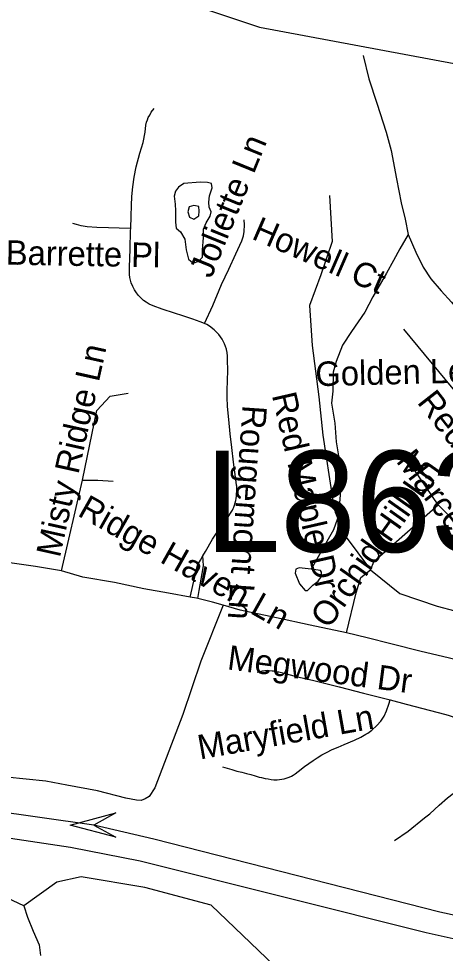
# Model space of a CAD drawing. Extents: x 1383679 to 1536984, y 460658 to 651027.
# Drawn here: x 1450610 to 1452269, y 483158 to 486789 of the extents above; entities that cross this region are included whole.
import ezdxf

# ---------------------------------------------------------------- set-up
doc = ezdxf.new("R2010")
doc.units = 0
for name, color, linetype in [('Exist Hydrographic Creek Single Shore', 7, 'Continuous'), ('Exist Hydrographic Misc Water Feature', 7, 'Continuous'), ('Exist Road Non-System Type 51', 7, 'Continuous'), ('Exist Road Non-System Type 51 Label', 7, 'Continuous'), ('Exist Road Primary Interstate Divided Center Attributed', 7, 'Continuous'), ('Exist Road Primary Interstate Structure Cantilever Sign Attributed CELL', 7, 'Continuous'), ('Exist Road Primary Interstate Structure Cantilever Sign Number Label', 7, 'Continuous')]:
    doc.layers.add(name, color=color, linetype=linetype)

msp = doc.modelspace()

# ---------------------------------------------------------------- linework, layer by layer
at = {"layer": 'Exist Hydrographic Creek Single Shore'}
for points in [[(1451305.3, 486835.8), (1451546.2, 486755.5), (1452401.3, 486597.1), (1452660.2, 486628), (1452879.2, 486715.5), (1453129.2, 486710.5), (1453286.3, 486658.1), (1453403.2, 486662.3), (1453504.2, 486735.7), (1454042.3, 487417.5)], [(1450631, 483341.9), (1450302.2, 483494.8), (1449922.4, 483518.4), (1449139, 483483.5), (1448970, 483355.2), (1448382.2, 482913), (1447997.1, 482655.5), (1447799, 482673.6), (1447552.4, 482785.6), (1447330.1, 482896.2), (1447225.8, 482956.7), (1446831, 483120.2), (1446515, 483238.6), (1446352.4, 483568.7), (1446248.7, 483809.2), (1446066, 484021), (1445953.2, 484107.5), (1445854.2, 484158.7)], [(1451604.2, 483110.8), (1451358.9, 483344.6), (1451101.1, 483413.1), (1450853.8, 483455.2), (1450759.1, 483434.2), (1450631, 483341.9)]]:
    msp.add_lwpolyline(points, dxfattribs=at)
at = {"layer": 'Exist Hydrographic Misc Water Feature'}
for points in [[(1451949.9, 486645.3), (1451972.3, 486555.4), (1452002.5, 486460.5), (1452038.5, 486348.1), (1452059.2, 486277.2), (1452079.2, 486166.8), (1452097.4, 486072.9), (1452112.4, 486010.2), (1452125.2, 485950.1)], [(1451316.6, 486153.4), (1451252.5, 486148.1), (1451232.2, 486134.6), (1451219.9, 486118.5), (1451215.5, 486098.8), (1451219, 486068.4), (1451220.5, 486043), (1451219.7, 485998.7), (1451223.3, 485974.8), (1451239.1, 485960.5), (1451256.5, 485932.2), (1451261.8, 485890.3), (1451271.1, 485854), (1451288.8, 485839.7), (1451311.1, 485846.6), (1451325.3, 485862.8), (1451325.7, 485889), (1451328.7, 485939), (1451329.2, 485971), (1451339.8, 485996.2), (1451354.3, 486022.2), (1451358.5, 486038.5), (1451350.9, 486056.7), (1451349.2, 486076.4), (1451351.7, 486100.2), (1451362.2, 486132), (1451360.5, 486148.4), (1451344.6, 486152.9), (1451316.6, 486153.4)], [(1451291, 486063.7), (1451272.8, 486057.5), (1451268.4, 486037.9), (1451274.1, 486018), (1451292, 486009.5), (1451310.3, 486023.1), (1451312.6, 486041.1), (1451311, 486059.1), (1451291, 486063.7)], [(1452125.2, 485950.1), (1452092.2, 485894.9), (1452067.4, 485849.4), (1452040.4, 485800), (1451986.8, 485708.3), (1451955.7, 485649), (1451904.3, 485573.7), (1451869.3, 485520.3), (1451844.2, 485456.8), (1451833.4, 485415.1), (1451832, 485341.3), (1451827.2, 485295.5), (1451839.8, 485217.3), (1451844.5, 485144.9), (1451853.4, 485090.6), (1451860, 485006.8), (1451860.7, 484938.6), (1451855.6, 484874.7), (1451848.9, 484842.9), (1451834.2, 484802.9), (1451803.2, 484749.4), (1451774.3, 484698.3), (1451747.4, 484650.4)], [(1452125.2, 485950.1), (1452154, 485881.4), (1452183, 485823.3), (1452212.2, 485778.4), (1452253.4, 485731.6), (1452292.6, 485687.4), (1452341.5, 485628.1), (1452392.1, 485550.8), (1452438.9, 485486.6), (1452476, 485433.4), (1452524.9, 485372.5), (1452571.8, 485314.1), (1452632.8, 485253), (1452672.1, 485213.6), (1452703.2, 485161.3), (1452720.3, 485115), (1452723.7, 485081.3), (1452713, 485043), (1452700.5, 485021), (1452661.8, 484974.2), (1452620.9, 484934.8), (1452590.3, 484899.3), (1452580, 484885.6)], [(1451747.4, 484650.4), (1451701.5, 484655.5), (1451687.3, 484650), (1451685.1, 484635.3), (1451702.3, 484593.1), (1451723.8, 484567.2), (1451733.9, 484567), (1451754.3, 484588.8), (1451774.6, 484603.9), (1451786.8, 484620.1), (1451787.2, 484638.1), (1451783.3, 484645.6), (1451747.4, 484650.4)], [(1450631, 483341.9), (1450644.1, 483298.1), (1450667.2, 483243.5), (1450690.3, 483191.3), (1450695.5, 483149.4)]]:
    msp.add_lwpolyline(points, dxfattribs=at)
at = {"layer": 'Exist Road Non-System Type 51'}
for points in [[(1451046, 485974), (1451047.5, 486021.8), (1451049.1, 486062.7), (1451050.9, 486098.6), (1451054.4, 486135.1), (1451059.9, 486173.8), (1451067.7, 486213.3), (1451081.4, 486266.7), (1451093.8, 486307.9), (1451102.2, 486348.3), (1451105.4, 486375.5), (1451108, 486386.5), (1451110.9, 486396.2), (1451114.1, 486404.4), (1451120.2, 486414.6), (1451125.8, 486425.2), (1451137.1, 486440.6)], [(1451818.5, 486101.7), (1451829.6, 485923.7), (1451785.1, 485793.9), (1451740.7, 485675.2), (1451751.8, 485519.4), (1451777.7, 485319.2), (1451792.6, 485170.8), (1451830.7, 484925.2), (1451840.3, 484872.1), (1451880, 484780.3), (1451977.9, 484647.9), (1452092.8, 484555.2), (1452237.3, 484507), (1452374.5, 484469.9), (1452456, 484469.9), (1452537.5, 484499.6), (1452611.7, 484558.9), (1452682.1, 484673.9), (1452700.6, 484796.3), (1452667.2, 484900.1), (1452541.2, 485059.6), (1452107.6, 485582.5)], [(1451046, 485974), (1451000.6, 485975.3), (1450959, 485976.1), (1450914.8, 485977.5), (1450877.1, 485980.3), (1450853.3, 485983.6), (1450835.2, 485988.9), (1450820.9, 485993.3)], [(1451333.4, 485604.1), (1451365, 485674.8), (1451399.5, 485755.6), (1451427.6, 485815.2), (1451455.3, 485875.6), (1451477.5, 485925.3), (1451484.4, 485945.7), (1451486.7, 485962.1), (1451487.8, 485988), (1451486.8, 486007.8)], [(1451333.4, 485604.1), (1451315.9, 485611.8), (1451287.8, 485621.7), (1451248.3, 485634.5), (1451216.4, 485645.4), (1451168.5, 485660.8), (1451133.7, 485673.1), (1451117.1, 485679.9), (1451105.7, 485687), (1451095.6, 485694.2), (1451085, 485703.9), (1451076.5, 485713), (1451068.6, 485723.6), (1451061.2, 485735.6), (1451054, 485748.4), (1451047.9, 485762.8), (1451044.6, 485773.6), (1451042.5, 485782.9), (1451040.8, 485795), (1451040.9, 485823.8), (1451043.3, 485893.5), (1451045.7, 485965.6), (1451046, 485974)], [(1451327, 484702.4), (1451336.3, 484719.5), (1451364.1, 484767.5), (1451385.1, 484797.8), (1451403.9, 484823.4), (1451421.4, 484848.1), (1451427.8, 484857.9), (1451434.3, 484868), (1451441.3, 484879.3), (1451444.8, 484886.6), (1451446.5, 484890.7), (1451449.5, 484898.8), (1451452.2, 484908), (1451454.2, 484916.5), (1451455.9, 484924.4), (1451456.9, 484934.2), (1451457.8, 484942.8), (1451458.6, 484952.8), (1451458.7, 484958.4), (1451458.6, 484965), (1451458.1, 484973), (1451457.8, 484976.9), (1451457.7, 484978.1), (1451448.7, 485046.6), (1451446, 485066), (1451439.4, 485122.4), (1451432.6, 485176.1), (1451427.3, 485231.9), (1451422.6, 485282.8), (1451421.4, 485318.5), (1451421.4, 485346.9), (1451421.9, 485381.2), (1451423.6, 485424.3), (1451422.8, 485460.9), (1451422.4, 485476.8), (1451420.9, 485492.8), (1451420.3, 485496.2), (1451417.8, 485505.3), (1451410.6, 485525.3), (1451401.8, 485543.5), (1451388.2, 485562.2), (1451370.1, 485580.1), (1451352.9, 485593.8), (1451341.4, 485600.6), (1451333.4, 485604.1)], [(1450777, 484644.2), (1450858.6, 484996.5), (1450914.2, 485267.2), (1450966.1, 485322.9), (1451036.5, 485334)], [(1452241, 484900.1), (1452148.4, 485037.3)], [(1450858.6, 484996.5), (1450917.9, 484996.5), (1450977.2, 484992.8)], [(1451977.9, 484647.9), (1451992.7, 484681.3), (1452241, 484900.1), (1452318.9, 484822.2)], [(1451277.5, 484541.8), (1451192.8, 484557.1), (1451096.9, 484574.4), (1450982.9, 484598.1), (1450859.4, 484618.9), (1450777, 484644.2), (1450675.7, 484660.1), (1450539.3, 484680), (1450440.8, 484694.3), (1450338.6, 484709), (1450226.3, 484724.1), (1450190.8, 484729.9)], [(1451277.5, 484541.8), (1451294.9, 484621), (1451305.8, 484665.5), (1451317.9, 484685.6), (1451327, 484702.4)], [(1451306.6, 484536.2), (1451311.5, 484567), (1451323.7, 484632.9), (1451328.8, 484663.6), (1451327.9, 484684.5), (1451327, 484702.1), (1451327, 484702.4)], [(1451885.2, 484403.1), (1451922.3, 484558.9), (1451940.8, 484618.2), (1451977.9, 484647.9)], [(1451306.6, 484536.2), (1451301.7, 484537.4), (1451277.5, 484541.8)], [(1451405.3, 484510.4), (1451363.4, 484522.6), (1451306.6, 484536.2)], [(1451405.3, 484510.4), (1451318, 484292.5), (1451249.1, 484086.3), (1451139.9, 483800.8), (1451118.3, 483766.8), (1451101.9, 483757.7), (1451086.8, 483752), (1451068.1, 483753.2), (1451027.2, 483761.1), (1450917.4, 483789.4), (1450797.1, 483811), (1450716, 483826.8), (1450484.7, 483850.6), (1450263.4, 483882.4), (1450059, 483903.9), (1449986.6, 483907.3)], [(1453518.2, 483999.8), (1453439.1, 484018.4), (1453304.4, 484052), (1453182.3, 484083.7), (1453044.7, 484117.7), (1452843.1, 484168.9), (1452751.6, 484190.4), (1452615.4, 484222.4), (1452487.3, 484252.3), (1452366, 484284.2), (1452280.8, 484305.4), (1452174.7, 484331.1), (1452057.4, 484360.6), (1451965.3, 484383.3), (1451885.2, 484403.1), (1451743.3, 484433), (1451613, 484460.9), (1451471.9, 484491.1), (1451405.3, 484510.4)], [(1451537.4, 484249.7), (1451543.4, 484251.5), (1451548.4, 484252.9), (1451554.3, 484254.6), (1451558.7, 484255.5), (1451561.9, 484255.9), (1451568, 484256.3), (1451573.5, 484256.3), (1451584.9, 484256.1), (1451595.8, 484255.7), (1451601.3, 484255.2), (1451606.2, 484254.6), (1451618.4, 484252.1), (1451621.5, 484251.2), (1451627.2, 484250), (1451642.2, 484246.2), (1451689, 484234), (1451757.7, 484217.3), (1451856, 484192.7), (1451950.5, 484168.8), (1452054.5, 484142.4)], [(1451402.4, 483882), (1451439.3, 483871.7), (1451458.5, 483866.2), (1451477.8, 483861.4), (1451496.2, 483856.5), (1451512.4, 483852.1), (1451529.9, 483847.3), (1451545.3, 483842.9), (1451554.7, 483840.7), (1451568.9, 483837.6), (1451579.8, 483835.3), (1451591.8, 483833.6), (1451602.8, 483832.3), (1451608.9, 483831.9), (1451615.2, 483832.1), (1451623.9, 483833), (1451633.1, 483834), (1451643.2, 483835.9), (1451650.8, 483838), (1451661.8, 483842), (1451670.8, 483846), (1451678, 483850.2), (1451684.9, 483855.1), (1451697.6, 483864.3), (1451721.8, 483883.8), (1451755.2, 483907.6), (1451770.3, 483917.6), (1451789.1, 483928.5), (1451806.9, 483938.1), (1451829.3, 483949.6), (1451852.2, 483959.3), (1451876, 483969), (1451915.9, 483985.4), (1451940.3, 483997.2), (1451953.8, 484005), (1451960.1, 484008.8), (1451967.7, 484013.5), (1451983.8, 484025.2), (1452003, 484042.5), (1452018, 484059.8), (1452031.4, 484079.9), (1452040.6, 484099.7), (1452049.7, 484125.3), (1452054.5, 484142.4)], [(1452054.5, 484142.4), (1452117, 484126.5), (1452212.1, 484101.6), (1452265.8, 484087.3), (1452280.3, 484083.1), (1452296.2, 484078.3), (1452308, 484073.4), (1452312.8, 484071.3), (1452323.3, 484066.1), (1452332.5, 484061.1), (1452343, 484054.4), (1452350.8, 484048.7), (1452359.6, 484041.1), (1452366.5, 484033.4), (1452377.2, 484020.4), (1452386.2, 484006.9), (1452391.5, 483997.9), (1452397.8, 483985.7), (1452402.2, 483974.8), (1452406.4, 483963.3), (1452430.7, 483885.8), (1452443.2, 483844.8)], [(1452071.3, 483596.1), (1452125, 483633), (1452188.8, 483683.9), (1452208.3, 483699.8), (1452245.3, 483733.5), (1452277, 483761.8), (1452299.9, 483779.2), (1452311.3, 483787.1), (1452321, 483793.4), (1452331.7, 483800.1), (1452338.4, 483804.1), (1452344.1, 483807), (1452351.4, 483810.8), (1452362.3, 483815.8), (1452375.7, 483822.3), (1452384.6, 483825.7), (1452393.2, 483829), (1452443.2, 483844.8)]]:
    msp.add_lwpolyline(points, dxfattribs=at)
at = {"layer": 'Exist Road Primary Interstate Divided Center Attributed'}
for points in [[(1455058.1, 483174.1), (1454856.2, 483163), (1454669.9, 483156.3), (1454250.6, 483127.5), (1453955.4, 483118.4), (1453391.7, 483122.5), (1452990.4, 483167.3), (1452697.6, 483220.6), (1452247.2, 483318.2), (1451136.4, 483601.3), (1450902.3, 483655.9), (1450490.8, 483714.5), (1450011.1, 483764.3), (1449962, 483766.7), (1449456.7, 483790), (1449281.9, 483785.1)], [(1449402.8, 483684.6), (1450153.6, 483654.6), (1450473.1, 483621.3), (1450812.5, 483570.2), (1451083.2, 483516.9), (1452194, 483238.3), (1452637.7, 483140.6), (1452937.2, 483087.4), (1453292.1, 483038.5), (1453656, 483018.5), (1454006.6, 483018.7), (1454303.8, 483032), (1454694.3, 483047.6), (1454913.9, 483056.4), (1455135.8, 483072)]]:
    msp.add_lwpolyline(points, dxfattribs=at)
at = {"layer": 'Exist Road Primary Interstate Structure Cantilever Sign Attributed CELL'}
msp.add_lwpolyline([(1450987.5, 483608.6), (1450810.8, 483655.9), (1450987.5, 483703.2), (1450902.3, 483655.9)], close=True, dxfattribs=at)

# ---------------------------------------------------------------- texts
at = {"layer": 'Exist Road Non-System Type 51 Label'}
for s, rotation, p in [('Joliette Ln', 67.8644, (1451359, 485776.5)), ('Howell Ct', 336.4764, (1451512.2, 485935.1)), ('Barrette Pl', 358.9957, (1450559.9, 485833.4)), ('Misty Ridge Ln', 77.4904, (1450770.5, 484692.2)), ('Golden Leaf Ct', 1.3412, (1451765, 485361.2)), ('Red Maple Dr', 282.881, (1451594.5, 485326.5)), ('Red Maple Dr', 308.0055, (1452156.5, 485298.2)), ('Rougemont Ln', 266.042, (1451481.2, 485289.4)), ('Marcella Dr', 307.3938, (1452074.7, 485069.5)), ('Orchid Hill Ln', 54.7365, (1451815.9, 484414.7)), ('Ridge Haven Ln', 330.5486, (1450835.4, 484860.2)), ('Megwood Dr', 352.5434, (1451418.5, 484261.4)), ('Maryfield Ln', 10.0743, (1451315.1, 483910.8))]:
    msp.add_text(s, height=95, rotation=rotation, dxfattribs=at).set_placement(p)
at = {"layer": 'Exist Road Primary Interstate Structure Cantilever Sign Number Label'}
msp.add_text('L863', height=393.7, dxfattribs=at).set_placement((1451335, 484716.8))

doc.saveas('drawing.dxf')
